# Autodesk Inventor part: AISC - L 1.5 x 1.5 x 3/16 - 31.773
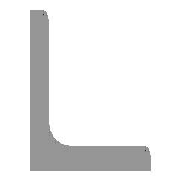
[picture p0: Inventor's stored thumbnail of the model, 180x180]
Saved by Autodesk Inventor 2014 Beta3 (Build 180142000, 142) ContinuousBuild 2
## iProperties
IsCustomPart: 1
Created: 2010-11
Part Number: AISC - L 1.5 x 1.5 x 3/16 - 31.773
Material: Steel, Mild
Description: Angle Steel
Document SubType Name: Modeling
Standard: ANSI
Designer: Beta-8540w
Standards Organization: ANSI
Language: en-US
Size Designation: L 1.5 x 1.5 x 3/16
Categories: <MemberInstance><Categories><Category DisplayName="Structural Shapes" InternalName="089c4875-fa83-4c05-b084-43b9cc11f5ed" Mnemonic="GRDR"><CategoryParameter Dis
Stock Number: L 1.5 x 1.5 x 3/16
Density: 7.86 g/cm^3
Appearance: Steel
G_L: 31.773 in
G_W: 1.500 in
G_H: 1.500 in
+B44689CE-99D4-45E6-A613-DBAE9BF7CE7B+CUTDETAIL1: Cut
_CCFamilyMember: 5
_CCFamilyDisplayName: ANSI L (Equal angles) - Angle Steel
_FrameMemberDoc: Frame Member File
_Version: 15.0.0
_GetPNFromCC: 1
Author: Beta-8540w
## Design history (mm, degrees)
node "Start plane"
node "End plane"
sketch "Sketch"
  geometry: L1 (38.1, 0)-(0, 0); L2 (0, 0)-(0, 38.1); L3 (0, 38.1)-(2.476, 38.1); L4 (4.762, 35.814)-(4.762, 9.589); L5 (9.588, 4.763)-(35.814, 4.763); L6 (38.1, 2.477)-(38.1, 0); L7 (0, -11.041)-(0, 31.538); L8 (-11.041, 0)-(31.538, 0); L9 (0, 48.496)-(0, -20.964) reference; L10 (-20.964, 0)-(48.496, 0) reference; A1 r 4.826 centre (9.588, 9.589) between (4.762, 9.589) and (9.588, 4.763); A2 r 2.286 centre (2.476, 35.814) between (4.762, 35.814) and (2.476, 38.1); A3 r 2.286 centre (35.814, 2.477) between (38.1, 2.477) and (35.814, 4.763); 3 further points
  constraints: 16 end point, 6 point on circle, 6 point on line, 6 tangent, 4 parallel, 3 centre point, 2 collinear, 1 equal radius, 1 horizontal, 1 perpendicular
  dimensions: "d0" = 38.1 distance between parallel lines of L6 L2 (= G_H); "d1" = 38.1 distance between parallel lines of L3 L1 (= G_H); "d2" = 4.7625 distance between parallel lines of L2 L4 (= G_T); "d3" = 4.7625 distance between parallel lines of L1 L5 (= G_T); "d10" = 0 distance between parallel lines of L7 L2 (computed from ex); "d11" = 0 distance between parallel lines of L8 L1 (computed from d10); "d14" = 4.826 radius of A1 (= G_IR); "d15" = 2.286 radius of A2 (= G_ER)
extrude "Body" new body sketch "Sketch" stored distance "d4" = 807.0404 (= G_L); taper "d5" = 0 deg
node "Driven Length"
  sketch "Sketch3"
    geometry: L1 (0, 0)-(10, 0) reference
    constraints: 2 end point, 1 horizontal
  workplane "Work Plane3"
  sketch "Sketch4"
    geometry: L1 (-2, 0)-(12, 0) reference; L2 (-2, 807.04)-(12, 807.04) reference
    dimensions: "d17" = 807.0404 distance between parallel lines of L1 L2 (derived)
workplane "Work Plane4"
split "Split1"
body "Solid1"
other parameters: "G_H" = 38.1 [user parameter; used in 2 equation terms], "G_T" = 4.7625 [user parameter; used in 2 equation terms], "G_ER" = 2.286 [user parameter; used in 1 equation term], "G_IR" = 4.826 [user parameter; used in 1 equation term], "G_L" = 807.0404 (= d17) [user parameter; used in 1 equation term], "ex" = 0 [user parameter; used in 1 equation term], "G_OFFSET_START" = 0 [user parameter; used in 1 equation term], "G_OFFSET_END" = -29.72503 [user parameter; used in 1 equation term], "d12" = 0 (computed from G_OFFSET_START), "d13" = 807.0404 (= G_OFFSET_END + B_L), "B_L" = 836.76542 [user parameter; used in 1 equation term], "d16" = 90 deg, "MAS" = 0.26787 [user parameter]
